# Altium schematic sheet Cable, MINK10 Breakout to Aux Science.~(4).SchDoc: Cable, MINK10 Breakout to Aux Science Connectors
size B; Organization: Monterey Bay Aquarium Research Institute; Address1: 7700 Sandholdt Rd; Address2: Moss Landing, CA 95039-9644; Revision: Initial; CheckedBy: Unchecked; CompanyName: MBARI; Engineer: Hans Thomas; Checked: Unchecked
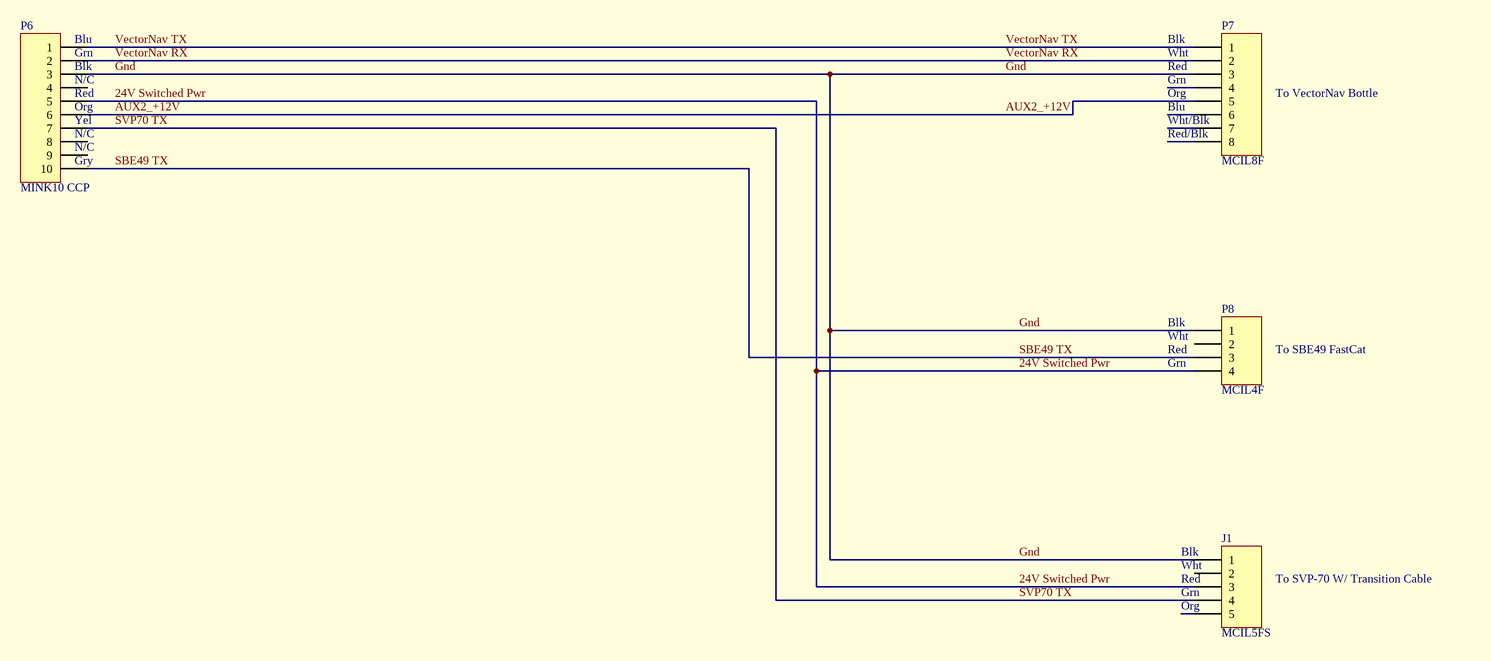
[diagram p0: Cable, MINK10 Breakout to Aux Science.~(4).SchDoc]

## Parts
J1  MCIL5FS  [HDR1X5]
P6  MINK10 CCP  [HDR1X10]
P7  MCIL8F  [HDR1X8]
P8  MCIL4F  [HDR1X4]

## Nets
24V Switched Pwr: J1.3 P6.5 P8.4
AUX2_+12V: P6.6 P7.5
Gnd: J1.1 P6.3 P7.3 P8.1
SBE49 TX: P6.10 P8.3
SVP70 TX: J1.4 P6.7
VectorNav RX: P6.2 P7.2
VectorNav TX: P6.1 P7.1

Not connected (* = marked no-connect by the designer): J1 2 5; P6 4 8 9; P7 4 6 7 8; P8 2

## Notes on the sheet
- (near P6) Blu
- (near P6) Grn
- (near P6) Blk
- (near P7) Red
- (near P7) Blk
- (near P7) Wht
- (near P6) N/C
- (near P6) Red
- (near P6) Org
- (near P6) Yel
- (near P7) Grn
- (near P7) Org
- (near P7) Blu
- (near P7) Wht/Blk
- (near P7) Red/Blk
- To VectorNav Bottle
- (near P6) Gry
- (near P8) Blk
- (near P8) Wht
- (near P8) Red
- (near P8) Grn
- To SBE49 FastCat
- (near J1) Red
- (near J1) Grn
- (near J1) Blk
- (near J1) Wht
- (near J1) Org
- To SVP-70 W/ Transition Cable

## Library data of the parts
J1 = Header 5: Header, 5-Pin
P6 = Header 10: Header, 10-Pin
P7 = Header 8: Header, 8-Pin
P8 = Header 4: Header, 4-Pin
